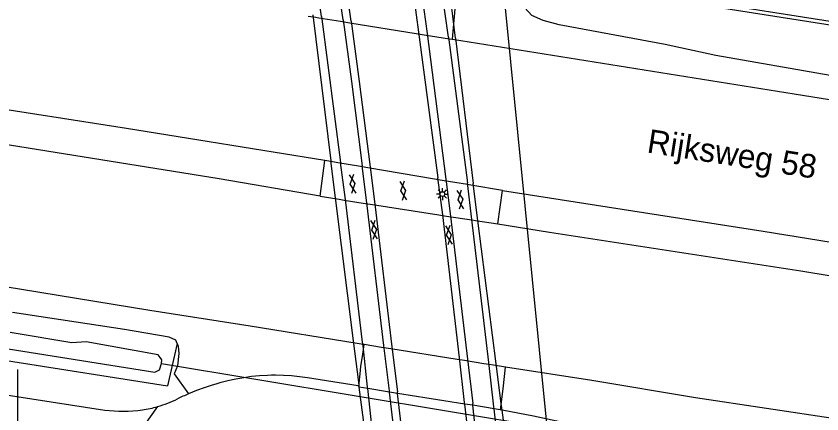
# Model space of a CAD drawing. Extents: x 132994 to 136000, y 393499 to 395512.
# Drawn here: x 133882.5 to 133967.7, y 394136.1 to 394178.1 of the extents above; entities that cross this region are included whole.
import ezdxf

# ---------------------------------------------------------------- set-up
doc = ezdxf.new("R2010")
doc.units = 0
for name, color, linetype in [('gg-afsc-muur', 7, 'Continuous'), ('gg-anno-openbare ruimte label', 7, 'Continuous'), ('gg-knt-bronhoudergrens', 7, 'Continuous'), ('gg-knt-verharding', 7, 'Continuous'), ('gg-knt-verharding niveau 01', 7, 'Continuous'), ('gg-kntw-bovenkant insteek waterloop', 7, 'Continuous'), ('gg-kwrk-duiker nz buis', 7, 'Continuous'), ('gg-kwrk-kunstwerk niveau 01', 7, 'Continuous'), ('gt-grn-weggrens', 7, 'Continuous'), ('gt-symb-gesloten verharding', 7, 'Continuous'), ('gt-symb-lichtmast', 7, 'Continuous'), ('gx-grn-maaiveld', 7, 'Continuous')]:
    doc.layers.add(name, color=color, linetype=linetype)

# ---------------------------------------------------------------- blocks, each defined once
blk = doc.blocks.new('gt0-GESVH1')
at = {"layer": 'gt-symb-gesloten verharding'}
for p, q in [((-0.992, -0.261), (0.008, 0.239)), ((0.008, -0.261), (-0.992, 0.239)), ((0.008, 0.239), (1.008, -0.261)), ((1.008, 0.239), (0.008, -0.261))]:
    blk.add_line(p, q, dxfattribs=at)
blk = doc.blocks.new('gt0-LMAST')
at = {"layer": 'gt-symb-lichtmast'}
for p, q in [((-0.182, 0.173), (-0.447, 0.438)), ((-0.005, 0.246), (-0.005, 0.621)), ((0.172, 0.173), (0.437, 0.438)), ((-0.255, -0.004), (-0.63, -0.004)), ((-0.182, -0.181), (-0.447, -0.446)), ((-0.005, -0.254), (-0.005, -0.629)), ((0.437, -0.446), (0.172, -0.181)), ((0.245, -0.004), (0.62, -0.004))]:
    blk.add_line(p, q, dxfattribs=at)
blk.add_circle((-0.005, -0.004), 0.25, dxfattribs=at)

msp = doc.modelspace()

# ---------------------------------------------------------------- linework, layer by layer
at = {"layer": 'gg-afsc-muur'}
msp.add_line((133953.915, 394179.869), (134000, 394172.585), dxfattribs=at)
msp.add_lwpolyline([(134000, 394172.207), (133940.882, 394181.505), (133941.044, 394182.549)], dxfattribs=at)
at = {"layer": 'gg-knt-bronhoudergrens'}
for p, q in [((133919.672, 394138.769), (133918.782, 394138.91)), ((133921.973, 394138.404), (133919.672, 394138.769)), ((133922.821, 394138.27), (133921.973, 394138.404)), ((133930.785, 394137.007), (133929.931, 394137.142)), ((133933.031, 394136.65), (133930.785, 394137.007)), ((133933.876, 394136.51), (133933.031, 394136.65))]:
    msp.add_line(p, q, dxfattribs=at)
for points in [[(133899.544, 394143.52), (133899.648, 394143.25), (133899.707, 394142.471), (133899.561, 394141.179), (133899.232, 394140.325), (133900.74, 394138.216)], [(133942.634, 394135.112), (133942.289, 394134.754), (133941.811, 394134.884), (133937.181, 394135.858), (133933.876, 394136.51)]]:
    msp.add_lwpolyline(points, dxfattribs=at)
at = {"layer": 'gg-knt-verharding'}
msp.add_line((133818.02, 394147.85), (133891.893, 394136.51), dxfattribs=at)
for centre, radius, start, end in [((133911.169, 394113.885), 26.472, 113.20206, 115.9946), ((133893.975, 394149.031), 12.654, 286.09098, 296.22691), ((133893.846, 394151.465), 15.082, 262.55831, 277.67278), ((133893.976, 394149.042), 12.665, 278.55373, 286.06966)]:
    msp.add_arc(centre, radius, start, end, dxfattribs=at)
at = {"layer": 'gg-knt-verharding niveau 01'}
for p, q in [((133917.067, 394177.69), (133915.88, 394186.274)), ((133917.908, 394177.554), (133916.719, 394186.144)), ((133923.897, 394185.035), (133925.043, 394176.401)), ((133924.759, 394184.902), (133925.946, 394176.255)), ((133925.043, 394176.401), (133927.085, 394161.007)), ((133925.946, 394176.255), (133927.931, 394160.872)), ((133919.58, 394158.386), (133919.087, 394162.288)), ((133919.927, 394162.154), (133920.418, 394158.252)), ((133927.595, 394157.105), (133927.085, 394161.007)), ((133927.931, 394160.872), (133928.426, 394156.972)), ((133921.386, 394143.309), (133919.58, 394158.386)), ((133920.418, 394158.252), (133922.232, 394143.172)), ((133929.361, 394142.02), (133927.595, 394157.105)), ((133928.426, 394156.972), (133930.209, 394141.883)), ((133921.957, 394138.547), (133921.386, 394143.309)), ((133922.232, 394143.172), (133922.804, 394138.413)), ((133929.912, 394137.312), (133929.361, 394142.02)), ((133930.209, 394141.883), (133930.765, 394137.185)), ((133921.973, 394138.404), (133921.957, 394138.547)), ((133922.457, 394134.21), (133921.973, 394138.404)), ((133922.821, 394138.27), (133922.804, 394138.413)), ((133923.305, 394134.089), (133922.821, 394138.27)), ((133929.931, 394137.142), (133929.912, 394137.312)), ((133930.385, 394133.078), (133929.931, 394137.142)), ((133930.785, 394137.007), (133930.765, 394137.185)), ((133931.236, 394132.957), (133930.785, 394137.007))]:
    msp.add_line(p, q, dxfattribs=at)
for points in [[(133917.067, 394177.69), (133917.961, 394171.18), (133919.087, 394162.288)], [(133917.908, 394177.554), (133918.782, 394171.19), (133919.927, 394162.154)]]:
    msp.add_lwpolyline(points, dxfattribs=at)
at = {"layer": 'gg-kntw-bovenkant insteek waterloop'}
msp.add_line((133899.544, 394143.52), (133898.511, 394139.051), dxfattribs=at)
at = {"layer": 'gg-kwrk-duiker nz buis'}
msp.add_line((133882.69, 394131.018), (133882.699, 394140.783), dxfattribs=at)
for points in [[(133891.668, 394187.796), (133933.967, 394181.078), (133938.555, 394135.07)], [(133897.865, 394141.413), (133938.589, 394134.682), (133978.323, 394128.352)]]:
    msp.add_lwpolyline(points, dxfattribs=at)
at = {"layer": 'gg-kwrk-kunstwerk niveau 01'}
for p, q in [((133928.19, 394175.885), (133927.022, 394184.552)), ((133928.655, 394178.081), (133927.883, 394184.419)), ((133914.782, 394178.059), (133914.073, 394183.413)), ((133913.861, 394178.208), (133915.788, 394162.817)), ((133914.782, 394178.059), (133916.808, 394162.653)), ((133928.938, 394175.762), (133928.655, 394178.081)), ((133928.19, 394175.885), (133930.198, 394160.509)), ((133928.938, 394175.762), (133930.808, 394160.411)), ((133916.277, 394158.914), (133915.788, 394162.817)), ((133917.322, 394158.747), (133916.808, 394162.653)), ((133930.679, 394156.612), (133930.198, 394160.509)), ((133931.297, 394156.513), (133930.808, 394160.411)), ((133918.166, 394143.829), (133916.277, 394158.914)), ((133919.137, 394143.672), (133917.322, 394158.747)), ((133932.457, 394141.526), (133930.679, 394156.612)), ((133933.245, 394141.401), (133931.297, 394156.513)), ((133918.716, 394139.434), (133918.166, 394143.829)), ((133919.181, 394143.273), (133919.137, 394143.672)), ((133919.657, 394138.91), (133919.181, 394143.273)), ((133933.008, 394136.851), (133932.457, 394141.526)), ((133933.788, 394137.189), (133933.245, 394141.401)), ((133918.764, 394139.051), (133918.716, 394139.434)), ((133918.782, 394138.91), (133918.764, 394139.051)), ((133919.316, 394134.658), (133918.782, 394138.91)), ((133919.672, 394138.769), (133919.657, 394138.91)), ((133920.135, 394134.541), (133919.672, 394138.769)), ((133933.848, 394136.726), (133933.788, 394137.189)), ((133933.031, 394136.65), (133933.008, 394136.851)), ((133933.481, 394132.636), (133933.031, 394136.65)), ((133933.876, 394136.51), (133933.848, 394136.726)), ((133934.393, 394132.506), (133933.876, 394136.51))]:
    msp.add_line(p, q, dxfattribs=at)
at = {"layer": 'gt-grn-weggrens'}
msp.add_line((133891.539, 394128.534), (133897.482, 394136.872), dxfattribs=at)
at = {"layer": 'gx-grn-maaiveld'}
for p, q in [((133928.628, 394175.65), (133929.407, 394184.183)), ((133914.651, 394159.097), (133915.157, 394162.844)), ((133933.424, 394156.147), (133933.898, 394159.682)), ((133881.513, 394141.735), (133898.511, 394139.051)), ((133918.671, 394139.066), (133913.302, 394139.914)), ((133918.721, 394138.996), (133918.671, 394139.066)), ((133918.721, 394138.996), (133918.782, 394138.91))]:
    msp.add_line(p, q, dxfattribs=at)
for points in [[(134008.443, 394165.332), (133980.599, 394169.716), (133956.44, 394173.925), (133951.093, 394175.106), (133939.892, 394177.171), (133938.195, 394177.627), (133937.027, 394178.138), (133936.27, 394178.957), (133935.675, 394180.079), (133935.407, 394181.001), (133935.062, 394181.991), (133934.575, 394182.782), (133933.999, 394183.274), (133933.291, 394183.556), (133932.837, 394183.656)], [(133913.38, 394178.096), (133914.201, 394177.964), (133914.522, 394177.913), (133916.789, 394177.549), (133917.764, 394177.393), (133924.795, 394176.265), (133925.633, 394176.13), (133928.323, 394175.699), (133928.619, 394175.652), (133928.628, 394175.65)], [(133915.157, 394162.844), (133894.196, 394166.211), (133861.663, 394171.308), (133821.517, 394177.769)], [(133928.628, 394175.65), (133964.718, 394169.882), (134019.207, 394161.173), (134023.173, 394160.539)], [(133914.651, 394159.097), (133903.98, 394160.9), (133873.23, 394165.84), (133844.46, 394170.46), (133822.09, 394173.99), (133820.751, 394174.205)], [(133933.898, 394159.682), (133930.571, 394160.243), (133930.201, 394160.306), (133927.538, 394160.755), (133926.726, 394160.892), (133919.701, 394162.077), (133918.712, 394162.244), (133916.509, 394162.616), (133916.146, 394162.677), (133915.157, 394162.844)], [(133919.309, 394143.412), (133919.156, 394143.436), (133918.967, 394143.466), (133918.565, 394143.531), (133907.264, 394145.344), (133896.655, 394147.029), (133885.032, 394148.916), (133872.065, 394151.018), (133859.394, 394153.058), (133847.511, 394154.942), (133838.306, 394156.399), (133825.615, 394158.468), (133818.361, 394159.644)], [(133933.898, 394159.682), (133961.448, 394155.384), (133992.392, 394150.389), (134024.721, 394145.209), (134061.356, 394139.292), (134097.887, 394133.551), (134126.32, 394129.036), (134168.919, 394122.251), (134195.279, 394118.103)], [(133914.651, 394159.097), (133916.645, 394158.761), (133917.018, 394158.697), (133917.18, 394158.67), (133919.2, 394158.356), (133920.191, 394158.203), (133927.201, 394157.114), (133928.005, 394156.989), (133930.656, 394156.577), (133931.043, 394156.517), (133933.424, 394156.147)], [(133933.424, 394156.147), (133938.88, 394155.3), (133965.44, 394151.19), (133993.658, 394146.55), (134009.251, 394143.915), (134025.05, 394141.472), (134039.715, 394139.102), (134059.532, 394135.97), (134074.358, 394133.521), (134091.387, 394130.893), (134103.814, 394128.799), (134116.882, 394126.724), (134131.68, 394124.43), (134143.263, 394122.577), (134157.303, 394120.286), (134173.672, 394117.607), (134193.402, 394114.391), (134194.734, 394114.178)], [(133899.544, 394143.52), (133899.404, 394143.882), (133898.696, 394144.192), (133893.984, 394144.998), (133882.149, 394146.79)], [(133881.67, 394142.979), (133897.183, 394140.518), (133897.668, 394140.736), (133897.865, 394141.413), (133897.907, 394141.811), (133897.738, 394142.039), (133897.523, 394142.324), (133889.939, 394143.713), (133888.406, 394143.591), (133881.885, 394144.694)], [(133918.721, 394138.996), (133918.902, 394140.69), (133918.95, 394141.137), (133919.109, 394142.146), (133919.309, 394143.412)], [(133934.232, 394141.042), (133932.977, 394141.238), (133932.518, 394141.31), (133931.948, 394141.399), (133929.896, 394141.726), (133929.119, 394141.85), (133922.117, 394142.964), (133921.113, 394143.124), (133919.309, 394143.412)], [(133933.876, 394136.51), (133933.714, 394136.542), (133933.985, 394138.733), (133934.232, 394141.042)], [(134021.139, 394127.176), (134020.04, 394127.352), (134011.608, 394128.7), (133999.298, 394130.713), (133984.378, 394133.182), (133969.325, 394135.547), (133954.308, 394137.811), (133943.338, 394139.619), (133934.232, 394141.042)], [(133905.732, 394139.774), (133904.89, 394139.588), (133904.054, 394139.373), (133903.64, 394139.256), (133903.226, 394139.131), (133902.406, 394138.861), (133901.596, 394138.564)], [(133913.302, 394139.914), (133912.464, 394140.028), (133911.623, 394140.11), (133910.779, 394140.16), (133909.934, 394140.177), (133909.511, 394140.173), (133909.088, 394140.161), (133908.244, 394140.113), (133907.403, 394140.032), (133906.565, 394139.919), (133905.732, 394139.774)], [(133901.596, 394138.564), (133901.167, 394138.394), (133900.74, 394138.216)], [(133929.931, 394137.142), (133927.719, 394137.493), (133922.821, 394138.27)]]:
    msp.add_lwpolyline(points, dxfattribs=at)

# ---------------------------------------------------------------- block references
at = {"layer": 'gt-symb-gesloten verharding'}
for p, rotation in [((133918.069, 394160.367), 97.12501634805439), ((133923.41, 394159.658), 97.06814005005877), ((133929.461, 394158.712), 97.12501634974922), ((133920.33, 394155.529), 96.89742755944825), ((133928.241, 394154.976), 96.89054832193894)]:
    msp.add_blockref('gt0-GESVH1', p, dxfattribs=dict(at, rotation=rotation))
at = {"layer": 'gt-symb-lichtmast'}
msp.add_blockref('gt0-LMAST', (133927.569, 394159.305), dxfattribs=at)

# ---------------------------------------------------------------- texts
at = {"layer": 'gg-anno-openbare ruimte label'}
msp.add_text('Rijksweg 58', height=2.5, rotation=351.1, dxfattribs=at).set_placement((133949.086, 394163.709))

doc.saveas('drawing.dxf')
